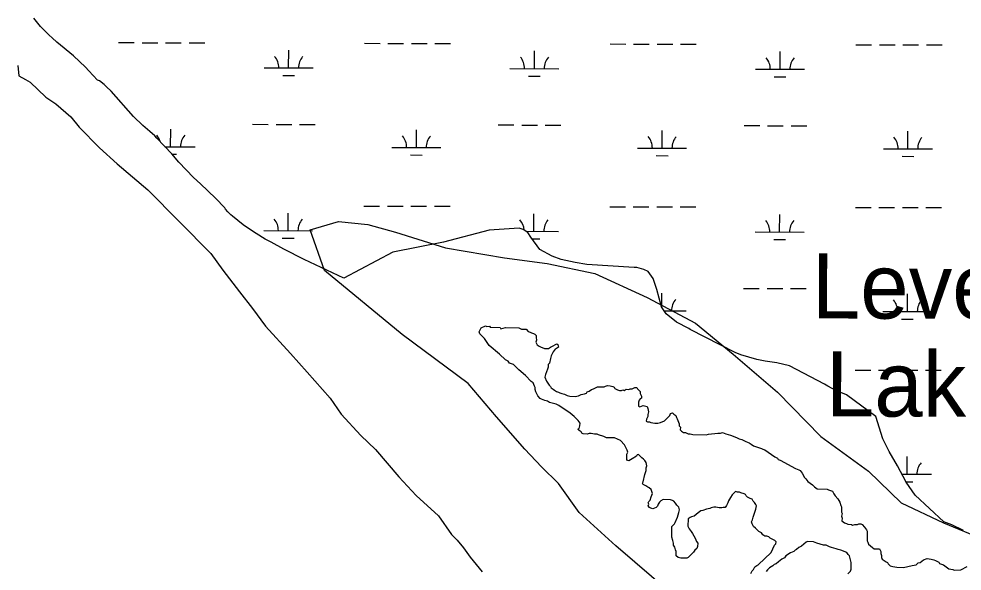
# Model space of a CAD drawing. Extents: x 3161615 to 3199515, y 867541 to 892976.
# Drawn here: x 3173988 to 3175914, y 881050 to 882179 of the extents above; entities that cross this region are included whole.
import ezdxf

# ---------------------------------------------------------------- set-up
doc = ezdxf.new("R2010")
doc.units = 0
for name, color, linetype in [('V-RIVR-IDEN', 7, 'Continuous'), ('V-SITE-VEGE', 7, 'Continuous'), ('V-TOPO-SHOR', 7, 'Continuous'), ('V-WETL-SWMP', 7, 'Continuous')]:
    doc.layers.add(name, color=color, linetype=linetype)

msp = doc.modelspace()

# ---------------------------------------------------------------- linework, layer by layer
at = {"layer": 'V-SITE-VEGE'}
for p, q in [((3173986, 882083.3), (3173987.8, 882062.4)), ((3173987.8, 882062.4), (3174001.1, 882054.7)), ((3174001.1, 882054.7), (3174010.6, 882049)), ((3174010.6, 882049), (3174042.8, 882018.4)), ((3174042.8, 882018.4), (3174063.6, 882005)), ((3174063.6, 882005), (3174093.9, 881978.2)), ((3174093.9, 881978.2), (3174110.9, 881957.2)), ((3174110.9, 881957.2), (3174152.6, 881915.2)), ((3174152.6, 881915.2), (3174188.5, 881882.6)), ((3174188.5, 881882.6), (3174251, 881829.1)), ((3174251, 881829.1), (3174379.7, 881699.1)), ((3174583, 881747.6), (3174640.9, 881764.7)), ((3174640.9, 881764.7), (3174700.5, 881758)), ((3174700.5, 881758), (3174756.7, 881742.8)), ((3174612.1, 881664.2), (3174583, 881747.6)), ((3174756.7, 881742.8), (3174858.9, 881710.6)), ((3174379.7, 881699.1), (3174404.3, 881664.8)), ((3174858.9, 881710.6), (3174979.9, 881690.3)), ((3174979.9, 881690.3), (3175066.7, 881678.5)), ((3174404.3, 881664.8), (3174438.3, 881620.9)), ((3174770.7, 881533.3), (3174612.1, 881664.2)), ((3175066.7, 881678.5), (3175163.8, 881658.3)), ((3175163.8, 881658.3), (3175271.2, 881609.1)), ((3174438.3, 881620.9), (3174464.7, 881586.5)), ((3175271.2, 881609.1), (3175370, 881556.4)), ((3174464.7, 881586.5), (3174491.2, 881550.2)), ((3174491.2, 881550.2), (3174542.3, 881494.8)), ((3175370, 881556.4), (3175446.8, 881493.5)), ((3174905.3, 881433.1), (3174770.7, 881533.3)), ((3174542.3, 881494.8), (3174576.3, 881456.6)), ((3175446.8, 881493.5), (3175537.2, 881415.3)), ((3174576.3, 881456.6), (3174623.6, 881403.1)), ((3174963.4, 881365), (3174905.3, 881433.1)), ((3175537.2, 881415.3), (3175625.9, 881325.2)), ((3174623.6, 881403.1), (3174646.2, 881370.7)), ((3174646.2, 881370.7), (3174686, 881326.8)), ((3175021.4, 881298.7), (3174963.4, 881365)), ((3174686, 881326.8), (3174716.2, 881298.1)), ((3175625.9, 881325.2), (3175723, 881253.9)), ((3174716.2, 881298.1), (3174763.5, 881242.7)), ((3175055.5, 881263), (3175021.4, 881298.7)), ((3175089.6, 881229), (3175055.5, 881263)), ((3174763.5, 881242.7), (3174799.5, 881204.5)), ((3175723, 881253.9), (3175789.6, 881189.3)), ((3175132.3, 881169.5), (3175089.6, 881229)), ((3174799.5, 881204.5), (3174844.9, 881162.4)), ((3175789.6, 881189.3), (3175876.5, 881148.5)), ((3174844.9, 881162.4), (3174871.3, 881124.2)), ((3175207.3, 881101.5), (3175132.3, 881169.5)), ((3175876.5, 881148.5), (3175970.2, 881109.5)), ((3174871.3, 881124.2), (3174882.7, 881112.8)), ((3174882.7, 881112.8), (3174895.9, 881097.5)), ((3175435.8, 880904.3), (3175207.3, 881101.5)), ((3174895.9, 881097.5), (3174909.2, 881078.4)), ((3174909.2, 881078.4), (3174933.7, 881047.9))]:
    msp.add_line(p, q, dxfattribs=at)
at = {"layer": 'V-TOPO-SHOR'}
for points in [[(3175273.2, 881189.6), (3175274.6, 881192.3), (3175277.4, 881195), (3175278.9, 881201.8), (3175281.7, 881208.6), (3175279.1, 881216.8), (3175275.1, 881219.6), (3175272.4, 881221), (3175268.3, 881223.9), (3175262.9, 881226.7), (3175261.6, 881229.4), (3175263, 881232.2), (3175266, 881247.1), (3175268.9, 881255.3), (3175269, 881260.8), (3175270.4, 881264.8), (3175269.2, 881271.7), (3175266.5, 881275.8), (3175263.8, 881278.6), (3175259.8, 881281.4), (3175253.1, 881288.4), (3175250.3, 881287.1), (3175248.9, 881284.4), (3175240.6, 881279), (3175233.7, 881275.1), (3175229.6, 881276.5), (3175229.8, 881288.8), (3175231.3, 881292.9), (3175230, 881297), (3175224.7, 881308), (3175216.7, 881316.4), (3175204.5, 881322.1), (3175188.1, 881322.3), (3175182.6, 881325.2), (3175171.8, 881328.1), (3175169, 881329.5), (3175163.6, 881329.6), (3175156.8, 881331.1), (3175152.7, 881331.2), (3175148.5, 881329.9), (3175140.3, 881330), (3175137.6, 881331.5), (3175136.3, 881334.2), (3175132.3, 881337), (3175129.6, 881339.8), (3175132.3, 881341.1), (3175133.8, 881346.6), (3175133.9, 881352), (3175129.9, 881357.6), (3175121.8, 881365.9), (3175113.8, 881372.9), (3175090.8, 881388.3), (3175085.4, 881391.2), (3175071.8, 881394.1), (3175067.7, 881397), (3175062.3, 881398.4), (3175055.5, 881401.3), (3175052.8, 881402.7), (3175047.4, 881408.3), (3175043.5, 881416.5), (3175042.2, 881420.7), (3175042.2, 881424.8), (3175040.9, 881427.5), (3175038.3, 881434.4), (3175034.3, 881437.2), (3175022.2, 881449.7), (3175008.7, 881460.9), (3174998, 881472), (3174989.8, 881474.9), (3174987.2, 881479.1), (3174981.7, 881481.9), (3174969.6, 881493), (3174948.1, 881511.2), (3174938.8, 881525), (3174929.4, 881534.8), (3174928.1, 881538.9), (3174932.3, 881547), (3174940.6, 881551), (3174943.3, 881549.6), (3174948.8, 881550.8), (3174950.1, 881548.1), (3174970.6, 881547.7), (3174971.9, 881544.9), (3174981.6, 881547.5), (3175008.9, 881547), (3175014.3, 881544.2), (3175023.9, 881544), (3175027.9, 881539.8), (3175032, 881538.4), (3175034.7, 881537), (3175038.8, 881535.5), (3175041.5, 881534.1), (3175044.1, 881531.3), (3175044.1, 881527.2), (3175045.3, 881521.8), (3175043.9, 881517.7), (3175046.5, 881512.2), (3175050.6, 881509.4), (3175053.3, 881507.9), (3175061.5, 881505.1), (3175069.7, 881504.9)], [(3175069.7, 881504.9), (3175073.8, 881507.6), (3175079.3, 881510.2), (3175083.5, 881512.9), (3175086.2, 881514.2), (3175088.9, 881512.8), (3175090.2, 881507.3), (3175086.1, 881504.6), (3175083.3, 881503.3), (3175079.1, 881497.9), (3175074.8, 881489.8), (3175073.4, 881484.3), (3175071.8, 881474.8), (3175069.1, 881472.1), (3175069, 881466.7), (3175067.5, 881462.6), (3175063.2, 881451.7), (3175061.8, 881446.3), (3175065.7, 881438), (3175071, 881429.7), (3175073.7, 881426.9), (3175075, 881424.2), (3175079.1, 881421.4), (3175081.8, 881419.9), (3175085.9, 881417.1), (3175089.9, 881415.7), (3175092.6, 881414.3), (3175096.7, 881412.8), (3175102.2, 881411.4), (3175107.6, 881408.5), (3175113, 881407.1), (3175123.9, 881406.9), (3175130.8, 881408.1), (3175136.3, 881410.8), (3175143.2, 881412), (3175147.3, 881413.3), (3175148.7, 881416), (3175152.8, 881417.3), (3175157, 881421.3), (3175161.1, 881422.6), (3175169.4, 881426.6), (3175183.1, 881426.3), (3175185.8, 881427.7), (3175190, 881428.9), (3175195.4, 881428.8), (3175200.9, 881427.4), (3175203.6, 881426), (3175204.9, 881423.2), (3175210.3, 881420.4), (3175214.4, 881418.9), (3175218.5, 881418.9), (3175221.2, 881420.2), (3175224, 881418.8), (3175228.1, 881421.4), (3175233.6, 881421.3), (3175236.3, 881422.6), (3175240.4, 881422.6), (3175245.9, 881425.2), (3175250, 881425.1), (3175251.4, 881422.4), (3175256.7, 881416.8), (3175256.7, 881412.7), (3175259.3, 881407.2), (3175259.2, 881403.1), (3175256.5, 881401.8), (3175255, 881399.1), (3175253.6, 881395), (3175253.5, 881386.8), (3175256.2, 881385.4), (3175263, 881388), (3175271.2, 881386.5), (3175272.5, 881382.4), (3175273.8, 881375.5), (3175272.3, 881370.1), (3175272.2, 881366), (3175269.4, 881360.5), (3175269.3, 881356.4), (3175272, 881355), (3175276.1, 881355), (3175278.8, 881353.5), (3175287, 881352), (3175292.5, 881351.9), (3175298, 881353.2), (3175306.2, 881357.1), (3175317.4, 881367.9), (3175318.8, 881372), (3175322.9, 881373.3), (3175325.6, 881370.5), (3175329.7, 881367.7), (3175331, 881363.5), (3175332.3, 881360.8), (3175336.2, 881351.1), (3175336.1, 881347), (3175338.8, 881344.3), (3175338.7, 881338.8), (3175341.4, 881336), (3175345.5, 881333.2), (3175349.6, 881333.1), (3175355, 881330.3), (3175359.1, 881330.2), (3175364.5, 881328.8)], [(3175364.5, 881328.8), (3175391.8, 881328.3), (3175396, 881329.6), (3175415.2, 881332), (3175420.6, 881331.9), (3175424.7, 881333.2), (3175431.5, 881330.3), (3175441, 881327.4), (3175453.3, 881323.1), (3175458.7, 881320.2), (3175464.1, 881318.8), (3175472.3, 881314.5), (3175479, 881311.7), (3175483.1, 881308.9), (3175488.5, 881306), (3175504.8, 881300.3), (3175507.5, 881298.9), (3175511.6, 881297.4), (3175531.9, 881283.4), (3175537.3, 881280.6), (3175538.6, 881277.8), (3175542.7, 881276.4)], [(3175542.7, 881276.4), (3175573.8, 881259.4), (3175580.6, 881256.5), (3175583.3, 881255.1), (3175587.3, 881249.6), (3175592.6, 881241.3), (3175595.3, 881238.5), (3175599.3, 881233), (3175608.7, 881226), (3175612.8, 881221.8), (3175618.2, 881217.6), (3175638.7, 881217.2), (3175641.4, 881215.8), (3175649.5, 881212.9), (3175652.2, 881207.4), (3175654.8, 881203.3), (3175660.2, 881197.7), (3175664.2, 881190.8), (3175666.8, 881183.9), (3175668.1, 881181.2), (3175667.9, 881170.2), (3175669.2, 881167.5), (3175667.8, 881162), (3175669, 881157.9), (3175668.9, 881152.4), (3175674.3, 881148.2), (3175678.4, 881146.8), (3175681.1, 881145.4), (3175688, 881145.3), (3175690.7, 881143.8), (3175694.8, 881145.1), (3175700.3, 881145), (3175703, 881146.4), (3175707.1, 881146.3), (3175709.8, 881144.9), (3175715.2, 881139.3), (3175719.2, 881133.8), (3175720.5, 881131), (3175720.2, 881111.9), (3175721.5, 881109.1), (3175722.8, 881105), (3175730.9, 881098), (3175734.9, 881095.2), (3175745.8, 881095), (3175748.5, 881089.5), (3175748.4, 881085.4), (3175749.7, 881081.3), (3175749.6, 881077.2), (3175750.9, 881074.4), (3175759, 881068.8), (3175761.8, 881067.4), (3175763.1, 881064.6), (3175767.1, 881060.5), (3175772.5, 881059), (3175780.7, 881057.5), (3175794.4, 881057.2), (3175812.2, 881061), (3175820.4, 881062.2), (3175824.6, 881066.3), (3175828.7, 881067.6), (3175835.7, 881072.9), (3175842.6, 881075.5), (3175850.7, 881074), (3175856.2, 881072.5), (3175860.2, 881071.1), (3175867, 881068.2), (3175868.3, 881065.5), (3175876.5, 881062.6), (3175887.3, 881054.2), (3175895.5, 881052.7), (3175898.2, 881051.3), (3175911.9, 881052.4), (3175924.3, 881059)], [(3175534.1, 881105.6), (3175534.2, 881109.7), (3175531.5, 881112.5), (3175527.5, 881114), (3175522, 881116.8), (3175519.4, 881119.6), (3175515.3, 881121), (3175511.2, 881121.1), (3175507.1, 881123.9), (3175504.5, 881128), (3175499.1, 881130.9), (3175492.3, 881137.8), (3175488.3, 881140.6), (3175485.7, 881146.1), (3175484.4, 881150.3), (3175485.8, 881154.3), (3175487.3, 881159.8), (3175493, 881176.1), (3175494.5, 881182.9), (3175493.2, 881185.7), (3175490.5, 881189.8), (3175487.8, 881192.6), (3175485.2, 881196.7), (3175481.1, 881198.2), (3175475.7, 881201), (3175473, 881203.8), (3175471.7, 881206.5), (3175469, 881208), (3175462.2, 881209.5), (3175459.5, 881210.9), (3175455.4, 881210.9), (3175451.3, 881212.4), (3175444.3, 881205.7), (3175441.5, 881200.3), (3175437.3, 881193.5), (3175435.8, 881189.4), (3175433, 881184), (3175430.2, 881179.9), (3175426.1, 881180), (3175423.4, 881178.7), (3175417.9, 881178.8), (3175411.1, 881180.3), (3175407, 881180.4), (3175401.5, 881179.1), (3175398.7, 881177.8), (3175391.9, 881176.5), (3175385, 881173.9), (3175380.9, 881172.6), (3175375.3, 881168.6), (3175367, 881161.9), (3175361.5, 881160.7), (3175358.8, 881159.4), (3175354.6, 881156.7), (3175354.3, 881141.7), (3175357, 881136.1), (3175361, 881130.6), (3175363.6, 881126.5), (3175368.9, 881116.8), (3175371.5, 881109.9), (3175374.2, 881107.1), (3175374.1, 881100.3), (3175372.7, 881096.2), (3175368.5, 881092.2), (3175365.7, 881088.1), (3175354.6, 881077.4), (3175351.8, 881076.1), (3175339.5, 881076.3), (3175334.1, 881077.8), (3175330, 881080.6), (3175330.2, 881090.1), (3175328.9, 881092.9), (3175327.6, 881098.4), (3175324.9, 881102.5), (3175325, 881106.6), (3175323.7, 881112.1), (3175321.1, 881119), (3175321.3, 881129.9), (3175321.5, 881140.9), (3175327.1, 881146.2), (3175328.5, 881149), (3175332.8, 881159.8), (3175335.7, 881169.3), (3175337.2, 881174.8), (3175335.9, 881180.3), (3175331.9, 881184.4), (3175329.2, 881188.6), (3175325.2, 881192.8), (3175322.5, 881194.2), (3175318.4, 881195.6), (3175303.4, 881195.9), (3175299.2, 881193.2), (3175296.4, 881190.5), (3175293.6, 881186.5), (3175292.2, 881182.4), (3175289.4, 881179.7), (3175282.5, 881177.1), (3175278.4, 881178.6), (3175275.7, 881180), (3175273, 881182.8), (3175274.5, 881186.8), (3175273.2, 881189.6)], [(3175482.5, 881045), (3175485.3, 881050.5), (3175488.1, 881053.1), (3175490.9, 881058.6), (3175495.1, 881061.2), (3175497.8, 881062.5), (3175524.3, 881088), (3175531.4, 881103), (3175534.1, 881105.6)], [(3175680.7, 881044.2), (3175686.2, 881049.6), (3175687.7, 881053.7), (3175687.9, 881067.3), (3175685.3, 881075.6), (3175684.1, 881081.1), (3175681.4, 881083.9), (3175678.7, 881088), (3175666.5, 881092.3), (3175661.1, 881093.8), (3175657, 881095.2), (3175647.5, 881098.1), (3175643.4, 881099.6), (3175640.7, 881101), (3175636.6, 881102.4), (3175631.1, 881102.5), (3175617.6, 881106.9), (3175610.8, 881109.7), (3175598.5, 881110), (3175595.7, 881108.6), (3175586, 881100.6), (3175580.5, 881098), (3175576.3, 881093.9), (3175573.6, 881092.6), (3175570.8, 881089.9), (3175563.9, 881087.3), (3175554.2, 881080.7), (3175551.4, 881076.6), (3175545.9, 881074), (3175538.9, 881068.6), (3175534.8, 881064.6), (3175530.7, 881063.3), (3175527.9, 881060.6), (3175521, 881056.7), (3175516.8, 881052.6), (3175514, 881048.6)]]:
    msp.add_lwpolyline(points, dxfattribs=at)
at = {"layer": 'V-WETL-SWMP'}
for p, q in [((3174032.3, 882163.3), (3174018.2, 882180.4)), ((3174049.4, 882145.6), (3174032.3, 882163.3)), ((3174056, 882140.2), (3174049.4, 882145.6)), ((3174065.5, 882131.4), (3174056, 882140.2)), ((3174099.7, 882103.3), (3174065.5, 882131.4)), ((3174191.6, 882130.2), (3174223.6, 882130.1)), ((3174239.6, 882130), (3174271.6, 882129.9)), ((3174287.6, 882129.9), (3174319.6, 882129.8)), ((3174335.6, 882129.8), (3174367.6, 882129.7)), ((3174693.5, 882128.8), (3174725.5, 882128.7)), ((3174741.5, 882128.6), (3174773.5, 882128.6)), ((3174789.5, 882128.5), (3174821.5, 882128.4)), ((3174837.5, 882128.4), (3174869.5, 882128.3)), ((3175195.4, 882127.4), (3175227.4, 882127.3)), ((3175243.4, 882127.3), (3175275.4, 882127.2)), ((3175291.4, 882127.1), (3175323.4, 882127)), ((3175339.4, 882127), (3175371.4, 882126.9)), ((3175697.3, 882126), (3175729.3, 882125.9)), ((3175745.3, 882125.9), (3175777.3, 882125.8)), ((3175793.3, 882125.7), (3175825.3, 882125.7)), ((3175841.3, 882125.6), (3175873.3, 882125.5)), ((3174123.8, 882080.2), (3174099.7, 882103.3)), ((3174538.8, 882078.5), (3174538.9, 882114.5)), ((3175040.7, 882077.1), (3175040.8, 882113.1)), ((3175542.6, 882075.7), (3175542.7, 882111.7)), ((3174130.9, 882072.4), (3174123.8, 882080.2)), ((3174148.4, 882053.7), (3174130.9, 882072.4)), ((3174488.8, 882078.6), (3174588.8, 882078.3)), ((3174990.7, 882077.2), (3175090.7, 882076.9)), ((3175492.6, 882075.8), (3175592.6, 882075.6)), ((3174152.2, 882051.8), (3174148.4, 882053.7)), ((3174162.2, 882044.3), (3174152.2, 882051.8)), ((3174526.7, 882063.1), (3174550.7, 882063)), ((3175028.6, 882061.7), (3175052.6, 882061.6)), ((3175530.5, 882060.3), (3175554.5, 882060.2)), ((3174167, 882039.9), (3174162.2, 882044.3)), ((3174176.4, 882030.6), (3174167, 882039.9)), ((3174221.8, 881979.2), (3174176.4, 882030.6)), ((3174241.2, 881961), (3174221.8, 881979.2)), ((3174255, 881948.7), (3174241.2, 881961)), ((3174265.4, 881939.9), (3174255, 881948.7)), ((3174297.8, 881917.3), (3174297.9, 881953.3)), ((3174465, 881963.2), (3174497, 881963.1)), ((3174513, 881963.1), (3174545, 881963)), ((3174561, 881963), (3174593, 881962.9)), ((3174799.7, 881915.9), (3174799.8, 881951.9)), ((3174966.9, 881961.9), (3174998.9, 881961.8)), ((3175014.9, 881961.7), (3175046.9, 881961.6)), ((3175062.9, 881961.6), (3175094.9, 881961.5)), ((3175301.6, 881914.5), (3175301.7, 881950.5)), ((3175468.8, 881960.5), (3175500.8, 881960.4)), ((3175516.8, 881960.3), (3175548.8, 881960.2)), ((3175564.8, 881960.2), (3175596.8, 881960.1)), ((3175803.6, 881913.1), (3175803.7, 881949.1)), ((3174269.6, 881935), (3174265.4, 881939.9)), ((3174299.9, 881902.6), (3174269.6, 881935)), ((3174286.2, 881917.3), (3174347.8, 881917.1)), ((3174749.7, 881916), (3174849.7, 881915.7)), ((3175251.6, 881914.6), (3175351.6, 881914.4)), ((3175753.6, 881913.2), (3175853.6, 881913)), ((3174314.5, 881886), (3174299.9, 881902.6)), ((3174300.6, 881901.8), (3174309.8, 881901.8)), ((3174787.7, 881900.5), (3174811.7, 881900.4)), ((3175289.6, 881899.1), (3175313.6, 881899)), ((3175791.5, 881897.7), (3175815.5, 881897.6)), ((3174344.8, 881854.6), (3174314.5, 881886)), ((3174359, 881841.3), (3174344.8, 881854.6)), ((3174389.3, 881811.9), (3174359, 881841.3)), ((3174408.3, 881792.3), (3174389.3, 881811.9)), ((3174692.6, 881796.1), (3174724.6, 881796)), ((3174740.6, 881796), (3174772.6, 881795.9)), ((3174788.6, 881795.8), (3174820.6, 881795.8)), ((3174836.6, 881795.7), (3174868.6, 881795.6)), ((3175194.5, 881794.7), (3175226.5, 881794.6)), ((3175242.5, 881794.6), (3175274.5, 881794.5)), ((3175290.5, 881794.5), (3175322.5, 881794.4)), ((3174410.1, 881789.4), (3174408.3, 881792.3)), ((3174414.4, 881784.5), (3174410.1, 881789.4)), ((3174420.5, 881778.1), (3174414.4, 881784.5)), ((3174423.9, 881775.6), (3174420.5, 881778.1)), ((3174446.2, 881757.9), (3174423.9, 881775.6)), ((3174537.8, 881745.8), (3174537.9, 881781.8)), ((3175039.7, 881744.4), (3175039.8, 881780.4)), ((3175338.5, 881794.3), (3175370.5, 881794.2)), ((3175541.6, 881743), (3175541.7, 881779)), ((3175696.4, 881793.3), (3175728.4, 881793.2)), ((3175744.4, 881793.2), (3175776.4, 881793.1)), ((3175792.4, 881793.1), (3175824.4, 881793)), ((3175840.4, 881792.9), (3175872.4, 881792.8)), ((3174461, 881747.5), (3174446.2, 881757.9)), ((3174472.4, 881739.6), (3174461, 881747.5)), ((3174491, 881728.6), (3174472.4, 881739.6)), ((3174487.8, 881745.9), (3174587.8, 881745.7)), ((3174948, 881746.5), (3174855.2, 881722.1)), ((3175009.6, 881750.9), (3174948, 881746.5)), ((3175017.8, 881748.4), (3175009.6, 881750.9)), ((3175027.4, 881742), (3175017.8, 881748.4)), ((3175023.7, 881744.5), (3175089.7, 881744.3)), ((3175033.1, 881732.5), (3175027.4, 881742)), ((3175491.6, 881743.2), (3175591.6, 881742.9)), ((3174503.4, 881722.2), (3174491, 881728.6)), ((3174528.7, 881707.7), (3174503.4, 881722.2)), ((3174525.8, 881730.4), (3174549.8, 881730.3)), ((3174855.2, 881722.1), (3174751.5, 881702.1)), ((3175052.1, 881706.9), (3175033.1, 881732.5)), ((3175035.7, 881729), (3175051.7, 881728.9)), ((3175529.6, 881727.6), (3175553.6, 881727.6)), ((3174570.7, 881686.7), (3174528.7, 881707.7)), ((3174751.5, 881702.1), (3174651.4, 881648.7)), ((3175077.2, 881693.6), (3175052.1, 881706.9)), ((3174651.4, 881648.7), (3174570.7, 881686.7)), ((3175095.4, 881687), (3175077.2, 881693.6)), ((3175123.7, 881680.6), (3175095.4, 881687)), ((3175147.8, 881676.3), (3175123.7, 881680.6)), ((3175244.4, 881670.7), (3175147.8, 881676.3)), ((3175250.2, 881670.2), (3175244.4, 881670.7)), ((3175264.2, 881666.4), (3175250.2, 881670.2)), ((3175273.1, 881662.4), (3175264.2, 881666.4)), ((3175283.3, 881648.2), (3175273.1, 881662.4)), ((3175290.7, 881625.4), (3175283.3, 881648.2)), ((3175300.6, 881589.8), (3175290.7, 881625.4)), ((3175467.9, 881627.8), (3175499.9, 881627.7)), ((3175515.9, 881627.7), (3175547.9, 881627.6)), ((3175563.9, 881627.5), (3175595.9, 881627.4)), ((3175300.7, 881589.6), (3175300.8, 881617.8)), ((3175802.6, 881580.4), (3175802.7, 881616.4)), ((3175310.1, 881575.6), (3175300.6, 881589.8)), ((3175305.9, 881581.8), (3175350.7, 881581.7)), ((3175330.8, 881558.5), (3175310.1, 881575.6)), ((3175752.6, 881580.6), (3175852.6, 881580.3)), ((3175790.6, 881565), (3175814.6, 881565)), ((3175355.9, 881545.5), (3175330.8, 881558.5)), ((3175358.6, 881543.5), (3175355.9, 881545.5)), ((3175450.5, 881496.3), (3175358.6, 881543.5)), ((3175462.1, 881491.8), (3175450.5, 881496.3)), ((3175494.7, 881482.3), (3175462.1, 881491.8)), ((3175512.2, 881478.8), (3175494.7, 881482.3)), ((3175535.9, 881475.3), (3175512.2, 881478.8)), ((3175561.9, 881469.4), (3175535.9, 881475.3)), ((3175633.3, 881431.9), (3175561.9, 881469.4)), ((3175695.5, 881460.7), (3175727.5, 881460.6)), ((3175743.5, 881460.5), (3175775.5, 881460.4)), ((3175791.5, 881460.4), (3175823.5, 881460.3)), ((3175839.5, 881460.3), (3175871.5, 881460.2)), ((3175640.2, 881427.5), (3175633.3, 881431.9)), ((3175656.1, 881419), (3175640.2, 881427.5)), ((3175677.9, 881410), (3175656.1, 881419)), ((3175738.1, 881365.8), (3175677.9, 881410)), ((3175752.2, 881319.8), (3175738.1, 881365.8)), ((3175765.4, 881294.1), (3175752.2, 881319.8)), ((3175782.5, 881265.2), (3175765.4, 881294.1)), ((3175801.7, 881247.8), (3175801.8, 881283.8)), ((3175799.9, 881231.6), (3175782.5, 881265.2)), ((3175791.6, 881247.8), (3175851.7, 881247.6)), ((3175799.6, 881232.3), (3175813.7, 881232.3)), ((3175818.2, 881204.7), (3175799.9, 881231.6)), ((3175876.8, 881150.4), (3175818.2, 881204.7)), ((3175893.5, 881144.3), (3175876.8, 881150.4)), ((3175916.8, 881132.9), (3175893.5, 881144.3))]:
    msp.add_line(p, q, dxfattribs=at)
for centre, start, end in [((3174483.5, 882079.1), 359.0699, 40.6135), ((3174594, 882078.8), 139.0699, 180.6135), ((3174985.4, 882077.7), 359.0699, 40.6135), ((3175095.9, 882077.4), 139.0699, 180.6135), ((3175487.3, 882076.3), 359.0699, 40.6135), ((3175597.8, 882076), 139.0699, 180.6135), ((3174242.6, 881917.9), 16.159, 40.6135), ((3174353.1, 881917.6), 139.0699, 180.6135), ((3174744.5, 881916.5), 359.0699, 40.6135), ((3174855, 881916.2), 139.0699, 180.6135), ((3175246.4, 881915.1), 359.0699, 40.6135), ((3175356.9, 881914.8), 139.0699, 180.6135), ((3175748.3, 881913.7), 359.0699, 40.6135), ((3175858.8, 881913.4), 139.0699, 180.6135), ((3174482.6, 881746.4), 359.0699, 40.6135), ((3174593.1, 881746.1), 139.0699, 180.6135), ((3174984.5, 881745), 3.4177, 40.6135), ((3175095, 881744.7), 139.0699, 180.6135), ((3175486.4, 881743.6), 359.0699, 40.6135), ((3175596.9, 881743.3), 139.0699, 180.6135), ((3175356, 881582.1), 139.0699, 180.6135), ((3175747.4, 881581.1), 359.0699, 40.6135), ((3175857.9, 881580.8), 139.0699, 180.6135), ((3175857, 881248.1), 139.0699, 180.6135)]:
    msp.add_arc(centre, 35.2, start, end, dxfattribs=at)

# ---------------------------------------------------------------- texts
at = {"layer": 'V-RIVR-IDEN'}
for s, p in [('Levee', (3175607.1, 881566.4)), ('Lake', (3175635.8, 881366.1))]:
    msp.add_text(s, height=133, rotation=359.8007, dxfattribs=at).set_placement(p)

doc.saveas('drawing.dxf')
